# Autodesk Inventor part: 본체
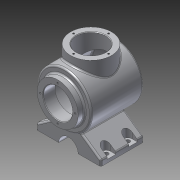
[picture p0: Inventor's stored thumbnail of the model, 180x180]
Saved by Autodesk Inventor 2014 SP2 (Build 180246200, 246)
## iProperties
Created: 2017-04
Part Number: 본체
Material: 알루미늄 6061
Document SubType Name: Modeling
Designer: 거성
Density: 2.71 g/cm^3
Appearance: 알루미늄 - 평지
Mass: 1670.47 g
Surface Area: 1064.89 cm^2
Volume: 616.411 cm^3
Author: 거성
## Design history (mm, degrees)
sketch "스케치4"
  geometry: L1 (0, -54)-(0, 54); L2 (0, 54)-(50, 54); L3 (50, 54)-(50, -42.336); L4 (0, 44)-(40, 44); L5 (40, 44)-(40, -35.916); L6 (0, -54)-(0, -44); L7 (0, 44)-(0, 54); A1 r 113 centre (0, 59) between (0, -54) and (50, -42.336); A2 r 103 centre (0, 59) between (0, -44) and (40, -35.916); 2 further points
  constraints: 14 end point, 4 point on circle, 2 centre point, 2 collinear, 2 parallel, 2 perpendicular, 1 coincident, 1 midpoint, 1 vertical
  dimensions: "d31" = 108 distance of L1.start L1.end; "d32" = 226 diameter of A1; "d33" = 100 diameter of L3 L1; "d34" = 50 distance from line of L3 A1.centre; "d35" = 10 radial gap between concentric circles of A1 A2; "d36" = 10 distance between parallel lines of L3 L5; "d37" = 10 distance between parallel lines of L2 L4
revolve "회전2" sketch "스케치4" stored, may be unused: angle "d38" = 90 deg
sketch "스케치5"
  geometry: C1 r 50 at (0, 0) reference; C2 r 38 at (0, 0)
  constraints: 1 centre point, 1 coincident
  dimensions: "d39" = 76 diameter of C2
extrude "돌출3" join sketch "스케치5" distance "d40" = 12; taper "d41" = 0 deg
sketch "스케치6"
  geometry: C1 r 38 at (0, 0) reference; C2 r 27 at (0, 0)
  constraints: 1 centre point, 1 coincident
  dimensions: "d42" = 54 diameter of C2
extrude "돌출4" cut sketch "스케치6" distance "d43" = 22; taper "d44" = 0 deg
node "작업 평면4"
sketch "스케치7"
  geometry: L1 (21.584, -45.101)-(60, -72); L2 (60, -72)-(60, -82); L3 (60, -82)-(-60, -82); L4 (-60, -82)-(-60, -72); L5 (-60, -72)-(-21.584, -45.101); A1 r 50 centre (0, 0) between (21.584, -45.101) and (-21.584, -45.101) reference; 2 further points
  constraints: 10 end point, 2 perpendicular, 2 point on circle, 1 midpoint, 1 parallel, 1 vertical, 1 vertical alignment
  dimensions: "d46" = 120 distance of L2.end L3.end; "d47" = 10 distance of L1.end L2.end; "d48" = 55 deg angle of L1 L2; "d49" = 55 deg angle of L4 L5; "d50" = 82 distance from line of L3 point (0, 0)
extrude "돌출5" join sketch "스케치7" distance "d51" = 80; taper "d52" = 0 deg
sketch "스케치8"
  geometry: L1 (-60, -82)-(60, -82) reference; C1 r 18 at (0, -82); 1 further point
  constraints: 1 centre point, 1 midpoint
  dimensions: "d53" = 36 diameter of C1
extrude "돌출6" cut sketch "스케치8" distance "d54" = 80; taper "d55" = 0 deg
node "작업 평면5"
sketch "스케치12" dims "d74" = 65
  geometry: C1 r 38 at (0, 0) reference; 2 further points
  constraints: 2 vertical alignment, 1 coincident, 2 other
hole "구멍2" sketch "스케치12" at (0, 32.5) diameter "d75" = 3.242; stored, may be unused: countersink angle "d79" = 82 deg, drill point angle "d81" = 118 deg; dims "d76" = 8, "d77" = 3.023, "d78" = 2, "d80" = 10
node "작업 평면6"
sketch "스케치13"
  geometry: L1 (-10, 68)-(0, 68); L2 (-10, 52)-(0, 52); L3 (-10, 28)-(0, 28); L4 (-10, 12)-(0, 12); L5 (0, 80)-(0, 0) reference; L6 (0, 80)-(-38.416, 80) reference; A1 r 8 centre (-10, 60) between (-10, 68) and (-10, 52); A2 r 8 centre (-10, 20) between (-10, 28) and (-10, 12); 1 further point
  constraints: 8 end point, 4 point on circle, 4 point on line, 4 tangent, 3 parallel, 2 centre point, 1 horizontal
  dimensions: "d86" = 16 diameter of A1; "d87" = 16 diameter of A2; "d88" = 10 distance from line of L5 A1.centre; "d89" = 20 distance from line of L6 A1.centre; "d90" = 40 distance of A2.centre A1.centre; "d91" = 10 distance of L4.start L4.end
extrude "돌출9" cut sketch "스케치13" distance "d92" = 40; taper "d93" = 0 deg
sketch "스케치14"
  geometry: C1 r 4 at (-10, -20); C2 r 4 at (-10, -60); A1 r 8 centre (-10, -20) between (-10, -12) and (-10, -28) reference; A2 r 8 centre (-10, -60) between (-10, -52) and (-10, -68) reference; 1 further point
  constraints: 2 centre point, 2 coincident
  dimensions: "d94" = 8 diameter of C1; "d95" = 8 diameter of C2
extrude "돌출10" cut sketch "스케치14" distance "d96" = 40; taper "d97" = 0 deg
fillet "모깎기2" dims "d99" = 3
fillet "모깎기3" dims "d100" = 3
fillet "모깎기4" dims "d101" = 3
fillet "모깎기5" dims "d102" = 3
node "작업 평면13"
sketch "스케치21"
  geometry: L1 (-50, 54)-(50, 54) reference; C1 r 38 at (0, 4); 1 further point
  constraints: 1 centre point, 1 vertical alignment
  dimensions: "d112" = 76 diameter of C1; "d113" = 50 distance from line of C1.centre L1
extrude "돌출11" join sketch "스케치21" stored distance "d114" = 40; taper "d115" = 0 deg
sketch "스케치22"
  geometry: C1 r 38 at (0, 0) reference; C2 r 27 at (0, 0); 1 further point
  constraints: 1 centre point, 1 coincident
  dimensions: "d116" = 54 diameter of C2
extrude "돌출12" cut sketch "스케치22" stored distance "d117" = 40; taper "d118" = 0 deg
sketch "스케치23" dims "d119" = 65
  geometry: C1 r 38 at (0, 0) reference; 3 further points
  constraints: 2 vertical alignment, 1 coincident, 2 other
hole "구멍3" sketch "스케치23" at (0, 32.5) diameter "d120" = 3.242; stored, may be unused: countersink angle "d124" = 82 deg, drill point angle "d126" = 118 deg; dims "d121" = 8, "d122" = 3.023, "d123" = 2, "d125" = 10
chamfer "모따기2" distance "d130" = 1; stored, may be unused: second distance "d131" = 2, angle "d132" = 45 deg
fillet "모깎기6" dims "d133" = 3
node "솔리드2"
pattern_circular "원형 패턴2" dims angle "d83" = 360 deg
mirror "대칭1"
pattern_circular "원형 패턴3" dims angle "d128" = 360 deg
other parameters: "d45" = -8, "d56" = 65, "d85" = -6, "d111" = 65
